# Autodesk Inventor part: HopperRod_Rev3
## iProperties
Created: 2009-01
Part Number: HopperRod_Rev3
Document SubType Name: Modeling
Designer: claivier
Material: Acier
Norme de conversion: STEP AP214IS
Nom du fichier: HopperRod_Rev3.STEP
Préprocesseur: SolidWorks 2008
Postprocesseur: Build: 344a, Release: 11 SP2 - Date: Fri 08/18/2006
Unités envoyées: INCHES
Incertitude: 1e-05
Author: claivier
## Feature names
1. Base1
